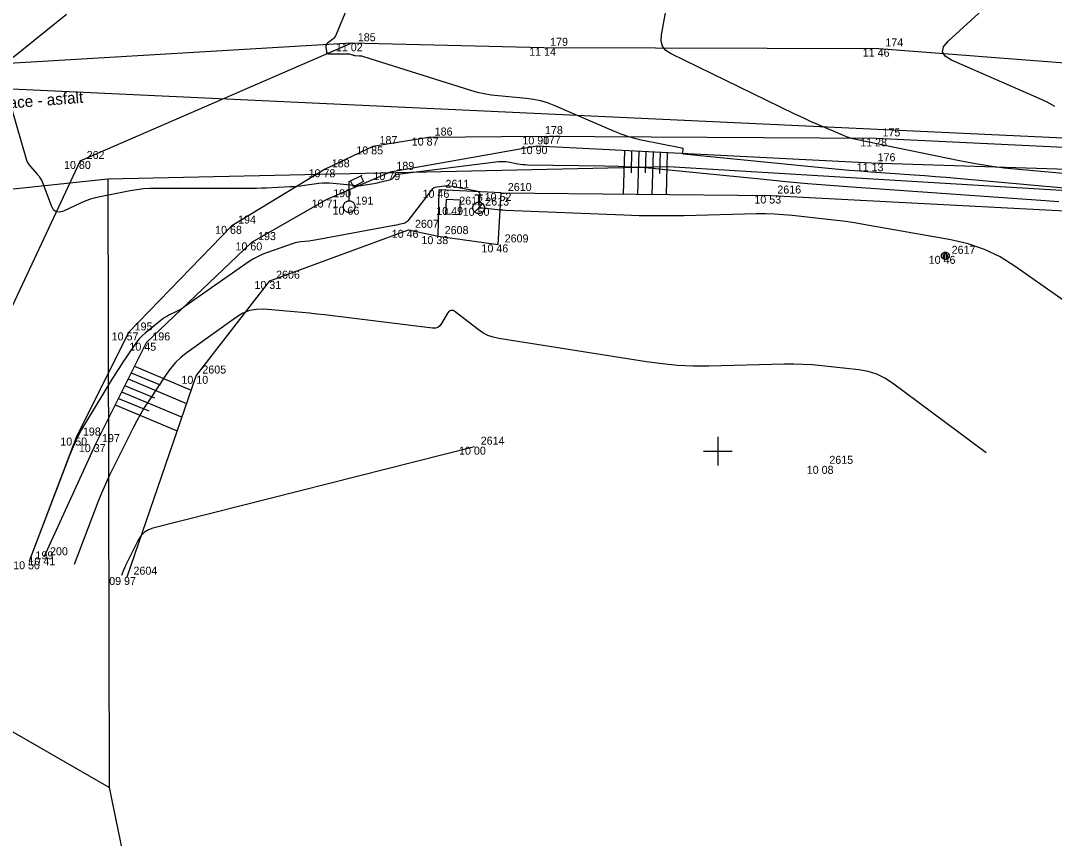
# Model space of a CAD drawing. Extents: x -703403 to -701924, y -1022520 to -1021856.
# Drawn here: x -702274.4 to -702238.23, y -1022288.55 to -1022259.93 of the extents above; entities that cross this region are included whole.
import ezdxf

# ---------------------------------------------------------------- set-up
doc = ezdxf.new("R2010")
doc.units = 0
for name, color, linetype in [('Ex_Major Contours', 7, 'Continuous'), ('Ex_Minor Contours', 7, 'Continuous'), ('Z_betonova_konstrukce', 7, 'Continuous'), ('Z_body', 7, 'Continuous'), ('Z_body_cisla', 7, 'Continuous'), ('Z_body_vysky_redukovane', 7, 'Continuous'), ('Z_hektometricka_sit', 7, 'Continuous'), ('Z_hrany_paty', 7, 'Continuous'), ('Z_katastr_hranice', 7, 'Continuous'), ('Z_komunikace', 7, 'Continuous'), ('Z_komunikace_osa', 7, 'Continuous'), ('Z_popisy', 7, 'Continuous'), ('Z_site_nerozlisene_znaky', 7, 'Continuous'), ('Z_site_vo_znaky', 7, 'Continuous'), ('Z_site_vodovod_znaky', 7, 'Continuous'), ('Z_sloupy', 7, 'Continuous'), ('Z_technicke_srafy', 7, 'Continuous')]:
    doc.layers.add(name, color=color, linetype=linetype)

# ---------------------------------------------------------------- blocks, each defined once
blk = doc.blocks.new('POINT_DISPLAY')
blk.add_line((0, 0), (0, 0))
blk = doc.blocks.new('Z18')
for p, q in [((-0.13, 0.45), (0.13, 0.45)), ((0, 0.2), (0, 0.45)), ((-0.2, 0.05), (-0.15, 0.15)), ((-0.2, -0.05), (-0.2, 0.05)), ((-0.15, 0.15), (-0.05, 0.2)), ((0.15, 0.15), (-0.15, -0.15)), ((-0.05, 0.2), (0.05, 0.2)), ((0.05, 0.2), (0.15, 0.15)), ((0.15, 0.15), (0.2, 0.05)), ((0.2, 0.05), (0.2, -0.05)), ((-0.15, -0.15), (-0.2, -0.05)), ((-0.05, -0.2), (-0.15, -0.15)), ((0.05, -0.2), (-0.05, -0.2)), ((0.15, -0.15), (0.05, -0.2)), ((0.2, -0.05), (0.15, -0.15))]:
    blk.add_line(p, q)
blk = doc.blocks.new('Z608')
for p, q in [((0.25, 0.25), (-0.25, 0.25)), ((-0.25, 0.25), (-0.25, -0.25)), ((0.25, -0.25), (0.25, 0.25)), ((-0.25, -0.25), (0.25, -0.25))]:
    blk.add_line(p, q)
blk = doc.blocks.new('Z601')
for p, q in [((-0.13, 0.03), (-0.1, 0.08)), ((-0.13, -0.03), (-0.13, 0.03)), ((-0.1, 0.08), (-0.08, 0.1)), ((-0.08, 0.1), (-0.03, 0.13)), ((-0.08, 0.05), (-0.08, -0.05)), ((-0.03, 0.13), (0.03, 0.13)), ((-0.03, -0.08), (-0.03, 0.08)), ((-0.03, 0.08), (0.03, 0.08)), ((0.03, 0.13), (0.08, 0.1)), ((0.03, 0.08), (0.03, -0.08)), ((0.08, 0.1), (0.1, 0.08)), ((0.08, -0.05), (0.08, 0.05)), ((0.1, 0.08), (0.13, 0.03)), ((0.13, 0.03), (0.13, -0.03)), ((-0.1, -0.08), (-0.13, -0.03)), ((-0.08, -0.1), (-0.1, -0.08)), ((-0.08, -0.05), (-0.03, -0.08)), ((-0.03, -0.13), (-0.08, -0.1)), ((0.03, -0.13), (-0.03, -0.13)), ((0.03, -0.08), (0.08, -0.05)), ((0.08, -0.1), (0.03, -0.13)), ((0.1, -0.08), (0.08, -0.1)), ((0.13, -0.03), (0.1, -0.08))]:
    blk.add_line(p, q)
blk = doc.blocks.new('Z13')
for p, q in [((0, 0.88), (0.45, 1.1)), ((0, 0.2), (0, 0.88)), ((0.15, 0.7), (0.05, 0.9)), ((0.5, 0.88), (0.15, 0.7)), ((0.4, 1.07), (0.5, 0.88)), ((-0.2, 0.05), (-0.15, 0.15)), ((-0.2, -0.05), (-0.2, 0.05)), ((-0.15, 0.15), (-0.05, 0.2)), ((-0.05, 0.2), (0.05, 0.2)), ((0.05, 0.2), (0.15, 0.15)), ((0.15, 0.15), (0.2, 0.05)), ((0.2, 0.05), (0.2, -0.05)), ((-0.15, -0.15), (-0.2, -0.05)), ((-0.05, -0.2), (-0.15, -0.15)), ((0.05, -0.2), (-0.05, -0.2)), ((0.15, -0.15), (0.05, -0.2)), ((0.2, -0.05), (0.15, -0.15))]:
    blk.add_line(p, q)

msp = doc.modelspace()

# ---------------------------------------------------------------- linework, layer by layer
at = {"layer": 'Ex_Major Contours'}
for points in [[(-702262.589, -1022258.53), (-702263.356, -1022260.41), (-702263.379, -1022260.457), (-702263.407, -1022260.5), (-702263.44, -1022260.539), (-702263.479, -1022260.574), (-702263.663, -1022260.722), (-702263.69, -1022260.749), (-702263.708, -1022260.78), (-702263.717, -1022260.815), (-702263.718, -1022260.853), (-702263.701, -1022261.014), (-702263.692, -1022261.049), (-702263.675, -1022261.074), (-702263.648, -1022261.09), (-702263.612, -1022261.095), (-702263.118, -1022261.096), (-702263.097, -1022261.096), (-702263.076, -1022261.095), (-702263.055, -1022261.095), (-702263.033, -1022261.094), (-702262.948, -1022261.09), (-702262.927, -1022261.09), (-702262.906, -1022261.092), (-702262.886, -1022261.095), (-702262.866, -1022261.101), (-702262.782, -1022261.13), (-702262.761, -1022261.137), (-702262.74, -1022261.142), (-702262.719, -1022261.145), (-702262.697, -1022261.147), (-702262.538, -1022261.156), (-702262.504, -1022261.159), (-702262.471, -1022261.164), (-702262.438, -1022261.171), (-702262.405, -1022261.18), (-702258.66, -1022262.359), (-702258.421, -1022262.427), (-702258.18, -1022262.482), (-702257.936, -1022262.524), (-702257.689, -1022262.553), (-702256.697, -1022262.643), (-702256.451, -1022262.675), (-702256.211, -1022262.726), (-702255.975, -1022262.797), (-702255.744, -1022262.886), (-702253.627, -1022263.801), (-702253.396, -1022263.893), (-702253.162, -1022263.973), (-702252.923, -1022264.041), (-702252.681, -1022264.096), (-702251.263, -1022264.379), (-702251.242, -1022264.386), (-702251.229, -1022264.398), (-702251.223, -1022264.415), (-702251.223, -1022264.437), (-702251.24, -1022264.533), (-702251.241, -1022264.554), (-702251.234, -1022264.57), (-702251.221, -1022264.581), (-702251.2, -1022264.586), (-702246.14, -1022265.09), (-702245.765, -1022265.126), (-702245.39, -1022265.159), (-702245.015, -1022265.19), (-702244.639, -1022265.218), (-702243.135, -1022265.324), (-702242.76, -1022265.352), (-702242.384, -1022265.381), (-702242.008, -1022265.412), (-702241.633, -1022265.444), (-702236.465, -1022265.904)], [(-702258.52, -1022274.84), (-702269.768, -1022277.688), (-702269.929, -1022277.746), (-702270.067, -1022277.833), (-702270.182, -1022277.949), (-702270.274, -1022278.094), (-702270.717, -1022278.979), (-702270.735, -1022279.015), (-702270.751, -1022279.052), (-702270.767, -1022279.089), (-702270.782, -1022279.127), (-702270.869, -1022279.353)]]:
    msp.add_lwpolyline(points, dxfattribs=at)
at = {"layer": 'Ex_Minor Contours'}
for points in [[(-702238.212, -1022262.928), (-702238.477, -1022262.779), (-702238.753, -1022262.648), (-702241.827, -1022261.31), (-702242.045, -1022261.177), (-702242.136, -1022261.022), (-702242.101, -1022260.847), (-702241.938, -1022260.65), (-702240.756, -1022259.564), (-702240.673, -1022259.481), (-702240.596, -1022259.393), (-702240.526, -1022259.3), (-702240.463, -1022259.202), (-702240.224, -1022258.796), (-702240.157, -1022258.707), (-702240.076, -1022258.643), (-702239.98, -1022258.603), (-702239.869, -1022258.589), (-702237.026, -1022258.536)], [(-702234.684, -1022265.566), (-702239.47, -1022265.141), (-702239.978, -1022265.088), (-702240.484, -1022265.021), (-702240.988, -1022264.94), (-702241.49, -1022264.844), (-702244.27, -1022264.27), (-702244.382, -1022264.247), (-702244.494, -1022264.224), (-702244.606, -1022264.202), (-702244.719, -1022264.179), (-702245.168, -1022264.089), (-702245.28, -1022264.064), (-702245.39, -1022264.033), (-702245.497, -1022263.996), (-702245.604, -1022263.954), (-702246.562, -1022263.539), (-702246.757, -1022263.454), (-702246.95, -1022263.366), (-702247.143, -1022263.277), (-702247.334, -1022263.185), (-702251.64, -1022261.095), (-702251.819, -1022260.977), (-702251.935, -1022260.826), (-702251.988, -1022260.644), (-702251.978, -1022260.429), (-702251.78, -1022259.339)], [(-702272.789, -1022259.715), (-702274.666, -1022261.222)], [(-702274.697, -1022263.079), (-702274.222, -1022264.734), (-702274.193, -1022264.816), (-702274.155, -1022264.894), (-702274.109, -1022264.967), (-702274.054, -1022265.035), (-702273.816, -1022265.298), (-702273.76, -1022265.366), (-702273.711, -1022265.438), (-702273.669, -1022265.515), (-702273.634, -1022265.595), (-702273.328, -1022266.403), (-702273.255, -1022266.535), (-702273.158, -1022266.609), (-702273.037, -1022266.624), (-702272.893, -1022266.581), (-702272.266, -1022266.29), (-702272.108, -1022266.222), (-702271.946, -1022266.164), (-702271.781, -1022266.116), (-702271.613, -1022266.078), (-702270.569, -1022265.875), (-702270.338, -1022265.836), (-702270.105, -1022265.808), (-702269.872, -1022265.792), (-702269.638, -1022265.787), (-702266.507, -1022265.794), (-702266.328, -1022265.793), (-702266.15, -1022265.79), (-702265.971, -1022265.784), (-702265.792, -1022265.777), (-702264.975, -1022265.737), (-702264.848, -1022265.729), (-702264.722, -1022265.718), (-702264.595, -1022265.705), (-702264.469, -1022265.689), (-702263.966, -1022265.619), (-702263.84, -1022265.606), (-702263.714, -1022265.6), (-702263.588, -1022265.602), (-702263.462, -1022265.612), (-702262.742, -1022265.692), (-702262.659, -1022265.698), (-702262.575, -1022265.699), (-702262.492, -1022265.694), (-702262.409, -1022265.683), (-702262.042, -1022265.624), (-702261.976, -1022265.612), (-702261.911, -1022265.6), (-702261.845, -1022265.586), (-702261.781, -1022265.57), (-702261.444, -1022265.488), (-702261.42, -1022265.479), (-702261.397, -1022265.467), (-702261.377, -1022265.452), (-702261.36, -1022265.432), (-702261.294, -1022265.348), (-702261.277, -1022265.329), (-702261.256, -1022265.314), (-702261.234, -1022265.304), (-702261.208, -1022265.299), (-702257.672, -1022264.863), (-702257.588, -1022264.855), (-702257.503, -1022264.855), (-702257.418, -1022264.861), (-702257.334, -1022264.873), (-702256.998, -1022264.936), (-702256.913, -1022264.95), (-702256.829, -1022264.96), (-702256.744, -1022264.967), (-702256.658, -1022264.97), (-702253.969, -1022265.008), (-702253.493, -1022265.02), (-702253.017, -1022265.042), (-702252.542, -1022265.074), (-702252.067, -1022265.116), (-702248.394, -1022265.482), (-702247.623, -1022265.556), (-702246.852, -1022265.625), (-702246.081, -1022265.688), (-702245.309, -1022265.745), (-702238.704, -1022266.212), (-702238.384, -1022266.236), (-702238.064, -1022266.26)], [(-702236.206, -1022270.91), (-702239.597, -1022268.528), (-702240.12, -1022268.201), (-702240.668, -1022267.937), (-702241.243, -1022267.736), (-702241.844, -1022267.597), (-702244.908, -1022267.062), (-702245.217, -1022267.011), (-702245.527, -1022266.964), (-702245.838, -1022266.923), (-702246.149, -1022266.886), (-702247.396, -1022266.749), (-702247.708, -1022266.72), (-702248.02, -1022266.702), (-702248.333, -1022266.693), (-702248.646, -1022266.696), (-702251.179, -1022266.757), (-702251.706, -1022266.766), (-702252.233, -1022266.766), (-702252.759, -1022266.757), (-702253.286, -1022266.739), (-702257.427, -1022266.568), (-702257.522, -1022266.563), (-702257.616, -1022266.557), (-702257.711, -1022266.549), (-702257.805, -1022266.54), (-702258.231, -1022266.495), (-702258.291, -1022266.48), (-702258.331, -1022266.449), (-702258.352, -1022266.403), (-702258.353, -1022266.341), (-702258.32, -1022266.063), (-702258.321, -1022266), (-702258.342, -1022265.952), (-702258.382, -1022265.918), (-702258.441, -1022265.898), (-702259.312, -1022265.735), (-702259.376, -1022265.725), (-702259.44, -1022265.721), (-702259.505, -1022265.721), (-702259.57, -1022265.727), (-702259.829, -1022265.759), (-702259.891, -1022265.772), (-702259.946, -1022265.797), (-702259.995, -1022265.832), (-702260.038, -1022265.878), (-702260.855, -1022266.937), (-702260.883, -1022266.968), (-702260.915, -1022266.993), (-702260.952, -1022267.013), (-702260.992, -1022267.026), (-702261.16, -1022267.067), (-702261.202, -1022267.077), (-702261.244, -1022267.087), (-702261.287, -1022267.096), (-702261.329, -1022267.104), (-702264.033, -1022267.603), (-702264.102, -1022267.615), (-702264.171, -1022267.626), (-702264.241, -1022267.635), (-702264.311, -1022267.643), (-702264.59, -1022267.672), (-702264.66, -1022267.681), (-702264.728, -1022267.694), (-702264.796, -1022267.711), (-702264.863, -1022267.732), (-702265.757, -1022268.038), (-702265.925, -1022268.102), (-702266.088, -1022268.178), (-702266.245, -1022268.265), (-702266.396, -1022268.363), (-702268.648, -1022269.938), (-702268.715, -1022269.983), (-702268.783, -1022270.025), (-702268.853, -1022270.064), (-702268.924, -1022270.1), (-702269.213, -1022270.241), (-702269.284, -1022270.278), (-702269.353, -1022270.319), (-702269.419, -1022270.363), (-702269.483, -1022270.412), (-702270.041, -1022270.865), (-702270.15, -1022270.961), (-702270.252, -1022271.065), (-702270.345, -1022271.176), (-702270.43, -1022271.295), (-702270.841, -1022271.919), (-702270.936, -1022272.064), (-702271.03, -1022272.21), (-702271.123, -1022272.357), (-702271.214, -1022272.504), (-702272.096, -1022273.942), (-702272.266, -1022274.235), (-702272.422, -1022274.534), (-702272.564, -1022274.84), (-702272.691, -1022275.153), (-702274.1, -1022278.85)], [(-702240.612, -1022275.057), (-702243.886, -1022272.613), (-702244.156, -1022272.438), (-702244.442, -1022272.302), (-702244.744, -1022272.206), (-702245.062, -1022272.15), (-702246.363, -1022272.008), (-702246.689, -1022271.977), (-702247.015, -1022271.958), (-702247.341, -1022271.95), (-702247.668, -1022271.952), (-702250.313, -1022272.016), (-702250.861, -1022272.017), (-702251.409, -1022271.993), (-702251.955, -1022271.945), (-702252.499, -1022271.871), (-702257.666, -1022271.056), (-702257.863, -1022271.012), (-702258.049, -1022270.946), (-702258.225, -1022270.855), (-702258.391, -1022270.742), (-702259.19, -1022270.12), (-702259.269, -1022270.075), (-702259.34, -1022270.069), (-702259.404, -1022270.101), (-702259.461, -1022270.172), (-702259.67, -1022270.534), (-702259.729, -1022270.612), (-702259.801, -1022270.663), (-702259.886, -1022270.689), (-702259.983, -1022270.69), (-702263.766, -1022270.227), (-702264.03, -1022270.196), (-702264.295, -1022270.168), (-702264.56, -1022270.142), (-702264.825, -1022270.119), (-702265.886, -1022270.032), (-702266.146, -1022270.033), (-702266.392, -1022270.077), (-702266.627, -1022270.167), (-702266.849, -1022270.301), (-702268.567, -1022271.543), (-702268.78, -1022271.711), (-702268.975, -1022271.897), (-702269.152, -1022272.099), (-702269.311, -1022272.319), (-702269.914, -1022273.232), (-702270.061, -1022273.462), (-702270.201, -1022273.696), (-702270.335, -1022273.934), (-702270.461, -1022274.177), (-702271.139, -1022275.531), (-702271.289, -1022275.84), (-702271.432, -1022276.152), (-702271.566, -1022276.467), (-702271.693, -1022276.786), (-702272.528, -1022278.961)]]:
    msp.add_lwpolyline(points, dxfattribs=at)
at = {"layer": 'Z_betonova_konstrukce'}
for p, q in [((-702259.79, -1022267.47), (-702259.75, -1022265.85)), ((-702257.58, -1022265.96), (-702259.75, -1022265.85)), ((-702257.69, -1022267.76), (-702257.58, -1022265.96)), ((-702259.79, -1022267.47), (-702257.69, -1022267.76))]:
    msp.add_line(p, q, dxfattribs=at)
at = {"layer": 'Z_hektometricka_sit'}
for p, q in [((-702250, -1022274.5), (-702250, -1022275.5)), ((-702250.5, -1022275), (-702249.5, -1022275))]:
    msp.add_line(p, q, dxfattribs=at)
at = {"layer": 'Z_hrany_paty'}
for p, q in [((-702256.34, -1022264.32), (-702261.47, -1022265.23)), ((-702244.63, -1022264.92), (-702256.34, -1022264.32)), ((-702261.47, -1022265.23), (-702263.68, -1022266.19)), ((-702232.55, -1022265.3), (-702244.63, -1022264.92)), ((-702257.58, -1022265.96), (-702248.14, -1022266.05)), ((-702263.68, -1022266.19), (-702266.32, -1022267.69)), ((-702248.14, -1022266.05), (-702235.99, -1022266.68)), ((-702265.68, -1022269.04), (-702260.83, -1022267.25)), ((-702260.83, -1022267.25), (-702259.79, -1022267.47)), ((-702266.32, -1022267.69), (-702270.01, -1022271.2)), ((-702268.26, -1022272.36), (-702265.68, -1022269.04)), ((-702270.01, -1022271.2), (-702271.78, -1022274.75)), ((-702270.67, -1022279.4), (-702268.26, -1022272.36)), ((-702271.78, -1022274.75), (-702273.59, -1022278.71))]:
    msp.add_line(p, q, dxfattribs=at)
at = {"layer": 'Z_katastr_hranice'}
for p, q in [((-702287.01, -1022261.74), (-702165.12, -1022267.43)), ((-702271.35, -1022265.46), (-702251.73, -1022265.03)), ((-702251.73, -1022265.03), (-702229.37, -1022266.38)), ((-702284.3, -1022266.86), (-702271.35, -1022265.46)), ((-702271.35, -1022265.46), (-702271.3, -1022286.77)), ((-702271.3, -1022286.77), (-702283.85, -1022279.53)), ((-702271.3, -1022286.77), (-702257.86, -1022352.18))]:
    msp.add_line(p, q, dxfattribs=at)
at = {"layer": 'Z_komunikace'}
for p, q in [((-702260.13, -1022264.02), (-702262.07, -1022264.33)), ((-702256.28, -1022263.98), (-702260.13, -1022264.02)), ((-702244.46, -1022264.05), (-702256.28, -1022263.98)), ((-702232.58, -1022264.63), (-702244.46, -1022264.05)), ((-702262.07, -1022264.33), (-702263.74, -1022265.13)), ((-702263.74, -1022265.13), (-702267.01, -1022267.11)), ((-702267.01, -1022267.11), (-702270.63, -1022270.84)), ((-702270.63, -1022270.84), (-702272.45, -1022274.52)), ((-702272.45, -1022274.52), (-702274.1, -1022278.85))]:
    msp.add_line(p, q, dxfattribs=at)
at = {"layer": 'Z_komunikace_osa'}
for p, q in [((-702262.83, -1022260.72), (-702276.27, -1022261.51)), ((-702272.32, -1022264.84), (-702262.83, -1022260.72)), ((-702256.09, -1022260.88), (-702262.83, -1022260.72)), ((-702244.37, -1022260.91), (-702256.09, -1022260.88)), ((-702232.49, -1022261.84), (-702244.37, -1022260.91)), ((-702272.32, -1022264.84), (-702275.51, -1022271.63))]:
    msp.add_line(p, q, dxfattribs=at)
at = {"layer": 'Z_technicke_srafy'}
for p, q in [((-702253.27, -1022264.48), (-702253.31, -1022266)), ((-702253.02, -1022264.49), (-702253.04, -1022265.25)), ((-702252.77, -1022264.5), (-702252.81, -1022266.01)), ((-702252.52, -1022264.52), (-702252.54, -1022265.26)), ((-702252.27, -1022264.53), (-702252.31, -1022266.01)), ((-702252.02, -1022264.54), (-702252.04, -1022265.28)), ((-702251.77, -1022264.55), (-702251.81, -1022266.01)), ((-702270.42, -1022272.02), (-702268.43, -1022272.86)), ((-702270.64, -1022272.47), (-702268.59, -1022273.33)), ((-702270.53, -1022272.25), (-702269.52, -1022272.67)), ((-702270.76, -1022272.7), (-702269.71, -1022273.13)), ((-702270.98, -1022273.15), (-702269.91, -1022273.59)), ((-702270.87, -1022272.92), (-702268.75, -1022273.81)), ((-702271.09, -1022273.37), (-702268.92, -1022274.28))]:
    msp.add_line(p, q, dxfattribs=at)

# ---------------------------------------------------------------- block references
at = {"layer": 'Z_body'}
for p in [(-702262.83, -1022260.72), (-702256.09, -1022260.88), (-702244.37, -1022260.91), (-702260.13, -1022264.02), (-702256.28, -1022263.98), (-702244.46, -1022264.05), (-702262.07, -1022264.33), (-702256.34, -1022264.32), (-702272.32, -1022264.84), (-702263.74, -1022265.13), (-702261.47, -1022265.23), (-702244.63, -1022264.92), (-702259.75, -1022265.85), (-702257.58, -1022265.96), (-702263.68, -1022266.19), (-702248.14, -1022266.05), (-702262.9, -1022266.44), (-702259.27, -1022266.45), (-702258.37, -1022266.48), (-702267.01, -1022267.11), (-702260.83, -1022267.25), (-702266.32, -1022267.69), (-702259.79, -1022267.47), (-702257.69, -1022267.76), (-702242.04, -1022268.16), (-702265.68, -1022269.04), (-702270.63, -1022270.84), (-702270.01, -1022271.2), (-702268.26, -1022272.36), (-702272.45, -1022274.52), (-702271.78, -1022274.75), (-702258.52, -1022274.84), (-702246.33, -1022275.51), (-702274.1, -1022278.85), (-702273.59, -1022278.71), (-702270.67, -1022279.4)]:
    msp.add_blockref('POINT_DISPLAY', p, dxfattribs=at)
at = {"layer": 'Z_site_nerozlisene_znaky', "rotation": -2.699999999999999}
msp.add_blockref('Z608', (-702259.27, -1022266.45), dxfattribs=at)
at = {"layer": 'Z_site_vo_znaky'}
msp.add_blockref('Z13', (-702262.9, -1022266.44), dxfattribs=at)
at = {"layer": 'Z_site_vodovod_znaky'}
msp.add_blockref('Z18', (-702258.37, -1022266.48), dxfattribs=at)
at = {"layer": 'Z_sloupy'}
msp.add_blockref('Z601', (-702242.04, -1022268.16), dxfattribs=at)

# ---------------------------------------------------------------- texts
at = {"layer": 'Z_body_cisla'}
for s, p in [('185', (-702262.6, -1022260.65)), ('179', (-702255.87, -1022260.81)), ('174', (-702244.14, -1022260.83)), ('186', (-702259.91, -1022263.95)), ('178', (-702256.05, -1022263.9)), ('175', (-702244.24, -1022263.98)), ('187', (-702261.84, -1022264.25)), ('177', (-702256.12, -1022264.24)), ('262', (-702272.09, -1022264.77)), ('188', (-702263.51, -1022265.06)), ('189', (-702261.25, -1022265.15)), ('176', (-702244.41, -1022264.85)), ('2611', (-702259.53, -1022265.78)), ('2610', (-702257.35, -1022265.89)), ('190', (-702263.46, -1022266.11)), ('2616', (-702247.92, -1022265.98)), ('191', (-702262.68, -1022266.37)), ('2612', (-702259.05, -1022266.37)), ('2613', (-702258.14, -1022266.4)), ('194', (-702266.79, -1022267.03)), ('2607', (-702260.6, -1022267.18)), ('193', (-702266.09, -1022267.61)), ('2608', (-702259.56, -1022267.4)), ('2609', (-702257.46, -1022267.69)), ('2617', (-702241.82, -1022268.09)), ('2606', (-702265.46, -1022268.96)), ('195', (-702270.41, -1022270.77)), ('196', (-702269.79, -1022271.12)), ('2605', (-702268.04, -1022272.28)), ('198', (-702272.22, -1022274.45)), ('197', (-702271.55, -1022274.68)), ('2614', (-702258.3, -1022274.77)), ('2615', (-702246.1, -1022275.44)), ('199', (-702273.88, -1022278.78)), ('200', (-702273.37, -1022278.64)), ('2604', (-702270.45, -1022279.32))]:
    msp.add_text(s, height=0.28, dxfattribs=at).set_placement(p)
at = {"layer": 'Z_body_vysky_redukovane'}
for s, p in [('11 02', (-702263.367, -1022261)), ('11 14', (-702256.603, -1022261.16)), ('11 46', (-702244.93, -1022261.19)), ('10 87', (-702260.713, -1022264.3)), ('10 90', (-702256.84, -1022264.26)), ('11 28', (-702245.02, -1022264.33)), ('10 85', (-702262.653, -1022264.61)), ('10 90', (-702256.9, -1022264.6)), ('10 80', (-702272.88, -1022265.12)), ('10 78', (-702264.323, -1022265.41)), ('10 79', (-702262.053, -1022265.51)), ('11 13', (-702245.143, -1022265.2)), ('10 46', (-702260.333, -1022266.13)), ('10 52', (-702258.163, -1022266.24)), ('10 71', (-702264.217, -1022266.47)), ('10 53', (-702248.723, -1022266.33)), ('10 66', (-702263.483, -1022266.72)), ('10 49', (-702259.853, -1022266.73)), ('10 50', (-702258.93, -1022266.76)), ('10 68', (-702267.593, -1022267.39)), ('10 46', (-702261.413, -1022267.53)), ('10 60', (-702266.88, -1022267.97)), ('10 38', (-702260.373, -1022267.75)), ('10 46', (-702258.273, -1022268.04)), ('10 46', (-702242.623, -1022268.44)), ('10 31', (-702266.217, -1022269.32)), ('10 57', (-702271.213, -1022271.12)), ('10 45', (-702270.593, -1022271.48)), ('10 10', (-702268.773, -1022272.64)), ('10 50', (-702273.01, -1022274.8)), ('10 37', (-702272.363, -1022275.03)), ('10 00', (-702259.057, -1022275.12)), ('10 08', (-702246.89, -1022275.79)), ('10 50', (-702274.66, -1022279.13)), ('10 41', (-702274.127, -1022278.99)), ('09 97', (-702271.3, -1022279.68))]:
    msp.add_text(s, height=0.28, dxfattribs=at).set_placement(p)
at = {"layer": 'Z_popisy'}
msp.add_text('Komunikace - asfalt', height=0.4, rotation=4.5, dxfattribs=at).set_placement((-702276.88, -1022263.17))

doc.saveas('drawing.dxf')
